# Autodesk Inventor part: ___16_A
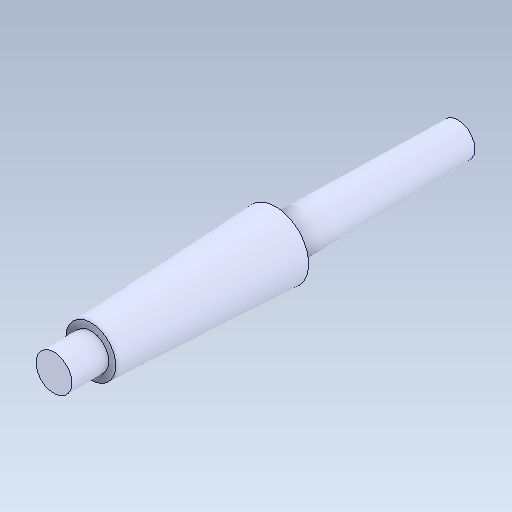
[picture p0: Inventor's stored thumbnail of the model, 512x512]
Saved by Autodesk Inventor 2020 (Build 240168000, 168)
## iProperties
Created: 2017-09
Part Number: ___16_A
Material: Générique
Document SubType Name: Modeling
Designer: bruno
Density: 1 g/cm^3
Appearance: Par défaut
Author: bruno
Sending System: SolidWorks 2016
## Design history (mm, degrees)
feature "Importée1"
node "Solide1"
